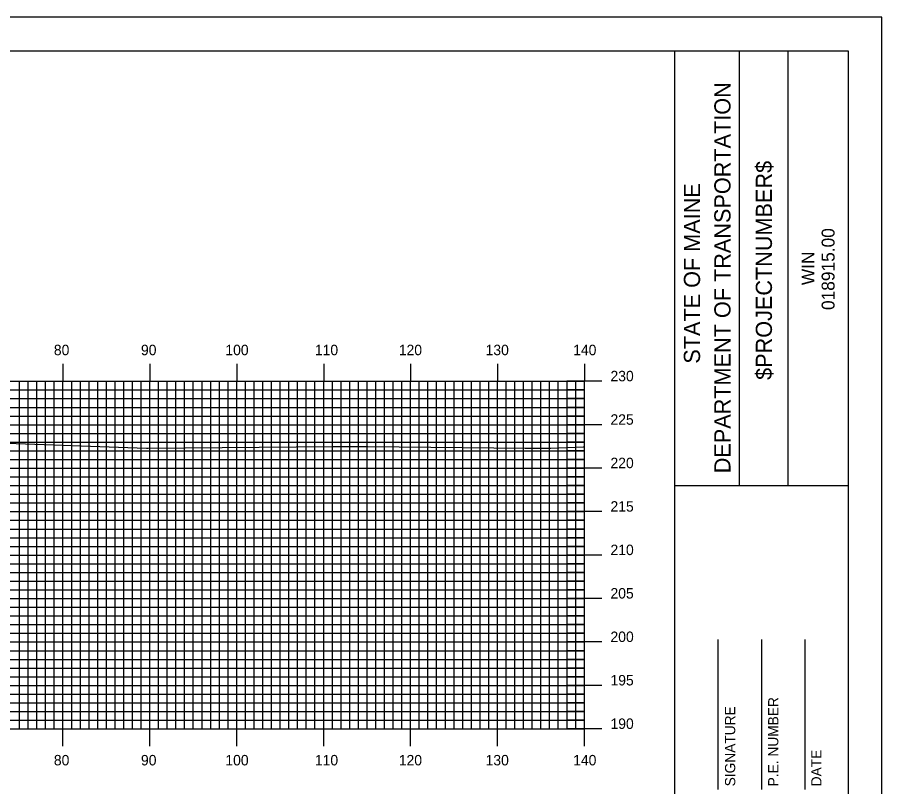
# Model space of a CAD drawing. Extents: x 1800749 to 1801092, y 442591 to 442811.
# Drawn here: x 1800989.3 to 1801088.8, y 442722 to 442810.5 of the extents above; entities that cross this region are included whole.
import ezdxf

# ---------------------------------------------------------------- set-up
doc = ezdxf.new("R2010")
doc.units = 0
for name, color, linetype in [('BORDER', 7, 'Continuous'), ('H_V ANNOTATION', 7, 'Continuous'), ('MAJOR', 7, 'Continuous'), ('MINOR', 7, 'Continuous'), ('PLOT BOUNDARY', 7, 'Continuous'), ('S_Roadway_Centerline', 7, 'Continuous')]:
    doc.layers.add(name, color=color, linetype=linetype)

msp = doc.modelspace()

# ---------------------------------------------------------------- linework, layer by layer
at = {"layer": 'BORDER'}
for p, q in [((1801064.949, 442596.665), (1801064.949, 442806.665)), ((1801072.406, 442756.659), (1801072.406, 442806.659)), ((1801077.997, 442756.659), (1801077.997, 442806.659)), ((1801064.951, 442756.653), (1801084.949, 442756.653)), ((1801069.949, 442721.671), (1801069.949, 442738.966)), ((1801074.949, 442721.671), (1801074.949, 442738.966)), ((1801079.949, 442721.671), (1801079.949, 442738.966))]:
    msp.add_line(p, q, dxfattribs=at)
msp.add_lwpolyline([(1800764.949, 442596.665), (1801084.949, 442596.665), (1801084.949, 442806.665), (1800764.949, 442806.665)], close=True, dxfattribs=at)
at = {"layer": 'MAJOR'}
for p, q in [((1800994.549, 442770.669), (1800994.549, 442768.665)), ((1801004.549, 442770.669), (1801004.549, 442768.665)), ((1801014.549, 442770.669), (1801014.549, 442768.665)), ((1801024.549, 442770.669), (1801024.549, 442768.665)), ((1801034.549, 442770.669), (1801034.549, 442768.665)), ((1801044.549, 442770.669), (1801044.549, 442768.665)), ((1801054.549, 442770.669), (1801054.549, 442768.665)), ((1800774.549, 442768.665), (1801054.549, 442768.665)), ((1800774.549, 442768.665), (1801054.549, 442768.665)), ((1800994.549, 442728.665), (1800994.549, 442768.665)), ((1801004.549, 442728.665), (1801004.549, 442768.665)), ((1801014.549, 442728.665), (1801014.549, 442768.665)), ((1801024.549, 442728.665), (1801024.549, 442768.665)), ((1801034.549, 442728.665), (1801034.549, 442768.665)), ((1801044.549, 442728.665), (1801044.549, 442768.665)), ((1801056.553, 442768.665), (1801052.545, 442768.665)), ((1801054.549, 442728.665), (1801054.549, 442768.665)), ((1801054.549, 442728.665), (1801054.549, 442768.665)), ((1800774.549, 442763.665), (1801054.549, 442763.665)), ((1801056.553, 442763.665), (1801052.545, 442763.665)), ((1800774.549, 442758.665), (1801054.549, 442758.665)), ((1801056.553, 442758.665), (1801052.545, 442758.665)), ((1800774.549, 442753.665), (1801054.549, 442753.665)), ((1801056.553, 442753.665), (1801052.545, 442753.665)), ((1800774.549, 442748.665), (1801054.549, 442748.665)), ((1801056.553, 442748.665), (1801052.545, 442748.665)), ((1800774.549, 442743.665), (1801054.549, 442743.665)), ((1801056.553, 442743.665), (1801052.545, 442743.665)), ((1800774.549, 442738.665), (1801054.549, 442738.665)), ((1801056.553, 442738.665), (1801052.545, 442738.665)), ((1800774.549, 442733.665), (1801054.549, 442733.665)), ((1801056.553, 442733.665), (1801052.545, 442733.665)), ((1800774.549, 442728.665), (1801054.549, 442728.665)), ((1800774.549, 442728.665), (1801054.549, 442728.665)), ((1800994.549, 442726.661), (1800994.549, 442728.665)), ((1801004.549, 442726.661), (1801004.549, 442728.665)), ((1801014.549, 442726.661), (1801014.549, 442728.665)), ((1801024.549, 442726.661), (1801024.549, 442728.665)), ((1801034.549, 442726.661), (1801034.549, 442728.665)), ((1801044.549, 442726.661), (1801044.549, 442728.665)), ((1801056.553, 442728.665), (1801052.545, 442728.665)), ((1801054.549, 442726.661), (1801054.549, 442728.665))]:
    msp.add_line(p, q, dxfattribs=at)
at = {"layer": 'MINOR'}
for p, q in [((1800989.549, 442728.665), (1800989.549, 442768.665)), ((1800990.549, 442728.665), (1800990.549, 442768.665)), ((1800991.549, 442728.665), (1800991.549, 442768.665)), ((1800992.549, 442728.665), (1800992.549, 442768.665)), ((1800993.549, 442728.665), (1800993.549, 442768.665)), ((1800995.549, 442728.665), (1800995.549, 442768.665)), ((1800996.549, 442728.665), (1800996.549, 442768.665)), ((1800997.549, 442728.665), (1800997.549, 442768.665)), ((1800998.549, 442728.665), (1800998.549, 442768.665)), ((1800999.549, 442728.665), (1800999.549, 442768.665)), ((1801000.549, 442728.665), (1801000.549, 442768.665)), ((1801001.549, 442728.665), (1801001.549, 442768.665)), ((1801002.549, 442728.665), (1801002.549, 442768.665)), ((1801003.549, 442728.665), (1801003.549, 442768.665)), ((1801005.549, 442728.665), (1801005.549, 442768.665)), ((1801006.549, 442728.665), (1801006.549, 442768.665)), ((1801007.549, 442728.665), (1801007.549, 442768.665)), ((1801008.549, 442728.665), (1801008.549, 442768.665)), ((1801009.549, 442728.665), (1801009.549, 442768.665)), ((1801010.549, 442728.665), (1801010.549, 442768.665)), ((1801011.549, 442728.665), (1801011.549, 442768.665)), ((1801012.549, 442728.665), (1801012.549, 442768.665)), ((1801013.549, 442728.665), (1801013.549, 442768.665)), ((1801015.549, 442728.665), (1801015.549, 442768.665)), ((1801016.549, 442728.665), (1801016.549, 442768.665)), ((1801017.549, 442728.665), (1801017.549, 442768.665)), ((1801018.549, 442728.665), (1801018.549, 442768.665)), ((1801019.549, 442728.665), (1801019.549, 442768.665)), ((1801020.549, 442728.665), (1801020.549, 442768.665)), ((1801021.549, 442728.665), (1801021.549, 442768.665)), ((1801022.549, 442728.665), (1801022.549, 442768.665)), ((1801023.549, 442728.665), (1801023.549, 442768.665)), ((1801025.549, 442728.665), (1801025.549, 442768.665)), ((1801026.549, 442728.665), (1801026.549, 442768.665)), ((1801027.549, 442728.665), (1801027.549, 442768.665)), ((1801028.549, 442728.665), (1801028.549, 442768.665)), ((1801029.549, 442728.665), (1801029.549, 442768.665)), ((1801030.549, 442728.665), (1801030.549, 442768.665)), ((1801031.549, 442728.665), (1801031.549, 442768.665)), ((1801032.549, 442728.665), (1801032.549, 442768.665)), ((1801033.549, 442728.665), (1801033.549, 442768.665)), ((1801035.549, 442728.665), (1801035.549, 442768.665)), ((1801036.549, 442728.665), (1801036.549, 442768.665)), ((1801037.549, 442728.665), (1801037.549, 442768.665)), ((1801038.549, 442728.665), (1801038.549, 442768.665)), ((1801039.549, 442728.665), (1801039.549, 442768.665)), ((1801040.549, 442728.665), (1801040.549, 442768.665)), ((1801041.549, 442728.665), (1801041.549, 442768.665)), ((1801042.549, 442728.665), (1801042.549, 442768.665)), ((1801043.549, 442728.665), (1801043.549, 442768.665)), ((1801045.549, 442728.665), (1801045.549, 442768.665)), ((1801046.549, 442728.665), (1801046.549, 442768.665)), ((1801047.549, 442728.665), (1801047.549, 442768.665)), ((1801048.549, 442728.665), (1801048.549, 442768.665)), ((1801049.549, 442728.665), (1801049.549, 442768.665)), ((1801050.549, 442728.665), (1801050.549, 442768.665)), ((1801051.549, 442728.665), (1801051.549, 442768.665)), ((1801052.549, 442728.665), (1801052.549, 442768.665)), ((1801053.549, 442728.665), (1801053.549, 442768.665)), ((1800774.549, 442767.665), (1801054.549, 442767.665)), ((1801054.549, 442767.665), (1801052.545, 442767.665)), ((1800774.549, 442766.665), (1801054.549, 442766.665)), ((1801054.549, 442766.665), (1801052.545, 442766.665)), ((1800774.549, 442765.665), (1801054.549, 442765.665)), ((1801054.549, 442765.665), (1801052.545, 442765.665)), ((1800774.549, 442764.665), (1801054.549, 442764.665)), ((1801054.549, 442764.665), (1801052.545, 442764.665)), ((1800774.549, 442762.665), (1801054.549, 442762.665)), ((1801054.549, 442762.665), (1801052.545, 442762.665)), ((1800774.549, 442761.665), (1801054.549, 442761.665)), ((1801054.549, 442761.665), (1801052.545, 442761.665)), ((1800774.549, 442760.665), (1801054.549, 442760.665)), ((1801054.549, 442760.665), (1801052.545, 442760.665)), ((1800774.549, 442759.665), (1801054.549, 442759.665)), ((1801054.549, 442759.665), (1801052.545, 442759.665)), ((1800774.549, 442757.665), (1801054.549, 442757.665)), ((1801054.549, 442757.665), (1801052.545, 442757.665)), ((1800774.549, 442756.665), (1801054.549, 442756.665)), ((1801054.549, 442756.665), (1801052.545, 442756.665)), ((1800774.549, 442755.665), (1801054.549, 442755.665)), ((1801054.549, 442755.665), (1801052.545, 442755.665)), ((1800774.549, 442754.665), (1801054.549, 442754.665)), ((1801054.549, 442754.665), (1801052.545, 442754.665)), ((1800774.549, 442752.665), (1801054.549, 442752.665)), ((1801054.549, 442752.665), (1801052.545, 442752.665)), ((1800774.549, 442751.665), (1801054.549, 442751.665)), ((1801054.549, 442751.665), (1801052.545, 442751.665)), ((1800774.549, 442750.665), (1801054.549, 442750.665)), ((1801054.549, 442750.665), (1801052.545, 442750.665)), ((1800774.549, 442749.665), (1801054.549, 442749.665)), ((1801054.549, 442749.665), (1801052.545, 442749.665)), ((1800774.549, 442747.665), (1801054.549, 442747.665)), ((1801054.549, 442747.665), (1801052.545, 442747.665)), ((1800774.549, 442746.665), (1801054.549, 442746.665)), ((1801054.549, 442746.665), (1801052.545, 442746.665)), ((1800774.549, 442745.665), (1801054.549, 442745.665)), ((1801054.549, 442745.665), (1801052.545, 442745.665)), ((1800774.549, 442744.665), (1801054.549, 442744.665)), ((1801054.549, 442744.665), (1801052.545, 442744.665)), ((1800774.549, 442742.665), (1801054.549, 442742.665)), ((1801054.549, 442742.665), (1801052.545, 442742.665)), ((1800774.549, 442741.665), (1801054.549, 442741.665)), ((1801054.549, 442741.665), (1801052.545, 442741.665)), ((1800774.549, 442740.665), (1801054.549, 442740.665)), ((1801054.549, 442740.665), (1801052.545, 442740.665)), ((1800774.549, 442739.665), (1801054.549, 442739.665)), ((1801054.549, 442739.665), (1801052.545, 442739.665)), ((1800774.549, 442737.665), (1801054.549, 442737.665)), ((1801054.549, 442737.665), (1801052.545, 442737.665)), ((1800774.549, 442736.665), (1801054.549, 442736.665)), ((1801054.549, 442736.665), (1801052.545, 442736.665)), ((1800774.549, 442735.665), (1801054.549, 442735.665)), ((1801054.549, 442735.665), (1801052.545, 442735.665)), ((1800774.549, 442734.665), (1801054.549, 442734.665)), ((1801054.549, 442734.665), (1801052.545, 442734.665)), ((1800774.549, 442732.665), (1801054.549, 442732.665)), ((1801054.549, 442732.665), (1801052.545, 442732.665)), ((1800774.549, 442731.665), (1801054.549, 442731.665)), ((1801054.549, 442731.665), (1801052.545, 442731.665)), ((1800774.549, 442730.665), (1801054.549, 442730.665)), ((1801054.549, 442730.665), (1801052.545, 442730.665)), ((1800774.549, 442729.665), (1801054.549, 442729.665)), ((1801054.549, 442729.665), (1801052.545, 442729.665))]:
    msp.add_line(p, q, dxfattribs=at)
at = {"layer": 'PLOT BOUNDARY'}
msp.add_lwpolyline([(1800748.763, 442590.547), (1801088.763, 442590.547), (1801088.763, 442810.547), (1800748.763, 442810.547)], close=True, dxfattribs=at)
at = {"layer": 'S_Roadway_Centerline'}
msp.add_lwpolyline([(1800982.683, 442761.738), (1801004.152, 442760.964), (1801004.169, 442760.962), (1801004.183, 442760.962), (1801004.344, 442760.963), (1801025.626, 442761.172), (1801027.547, 442761.15), (1801029.642, 442761.148), (1801047.716, 442760.956), (1801050.688, 442760.958), (1801054.41, 442761.125), (1801054.549, 442761.13)], dxfattribs=at)

# ---------------------------------------------------------------- texts
at = {"layer": 'BORDER'}
for s, height, p in [('DEPARTMENT OF TRANSPORTATION', 1.86351, (1801071.363, 442758.077)), ('$PROJECTNUMBER$', 1.86351, (1801076.133, 442768.823)), ('STATE OF MAINE', 1.86351, (1801067.86, 442770.689)), ('018915.00', 1.4905, (1801083.34, 442776.861)), ('WIN', 1.4905, (1801081.023, 442779.725)), ('P.E. NUMBER', 1.1811, (1801076.871, 442722.055)), ('SIGNATURE', 1.1811, (1801071.91, 442722.055)), ('DATE', 1.1811, (1801081.831, 442722.055))]:
    msp.add_text(s, height=height, rotation=90, dxfattribs=at).set_placement(p)
at = {"layer": 'H_V ANNOTATION'}
for s, p in [('80', (1800993.5, 442771.665)), ('90', (1801003.522, 442771.665)), ('100', (1801013.233, 442771.665)), ('110', (1801023.533, 442771.665)), ('120', (1801033.19, 442771.665)), ('130', (1801043.179, 442771.665)), ('140', (1801053.254, 442771.665)), ('230', (1801057.549, 442768.665)), ('225', (1801057.549, 442763.665)), ('220', (1801057.549, 442758.665)), ('215', (1801057.549, 442753.665)), ('210', (1801057.549, 442748.665)), ('205', (1801057.549, 442743.665)), ('200', (1801057.549, 442738.665)), ('195', (1801057.549, 442733.665)), ('190', (1801057.549, 442728.665)), ('80', (1800993.5, 442724.465)), ('90', (1801003.522, 442724.465)), ('100', (1801013.233, 442724.465)), ('110', (1801023.533, 442724.465)), ('120', (1801033.19, 442724.465)), ('130', (1801043.179, 442724.465)), ('140', (1801053.254, 442724.465))]:
    msp.add_text(s, height=1.2, dxfattribs=at).set_placement(p)

doc.saveas('drawing.dxf')
